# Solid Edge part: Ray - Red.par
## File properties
Author: hhakima
Template: Normal.par
Last saved by: hhakima
Revision: 8
Application: Solid Edge
Accuracy: 0.990
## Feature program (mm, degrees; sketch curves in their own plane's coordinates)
sketch for "unnamed Protrusion 1" plane through (0, 0, 0) normal (0, -1, 0) x-axis (1, 0, 0)
  circle centre (0, 0) radius 1.2
extrude "unnamed Protrusion 1" add finite 10.6 along -normal
sketch for "ExtrudedProtrusion_2" plane through (0, 0, 1.2) normal (1, 0, 0) x-axis (0, 1, 0)
extrude "ExtrudedProtrusion_2" add finite 39 along +normal
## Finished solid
Body 1: solid body, 7 faces, 10 edges, 5 vertices.
  Faces by surface: plane 5, cylinder 2
  Edges by curve: circle 5, intersection 3, line 2
Bounding box of the edges (mm): 40.200 x 10.600 x 2.500, from (-1.2, 0, -1.25) to (39, 10.6, 1.25).
Cylindrical faces by radius (mm): R1.2 x1, R1.25 x1
Planar faces by outward normal: +x 1, +y 1, -x 2, -y 1
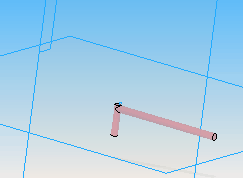
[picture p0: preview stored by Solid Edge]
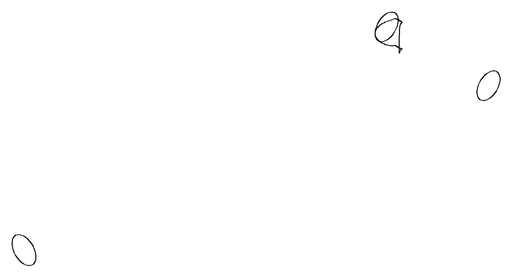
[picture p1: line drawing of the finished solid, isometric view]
